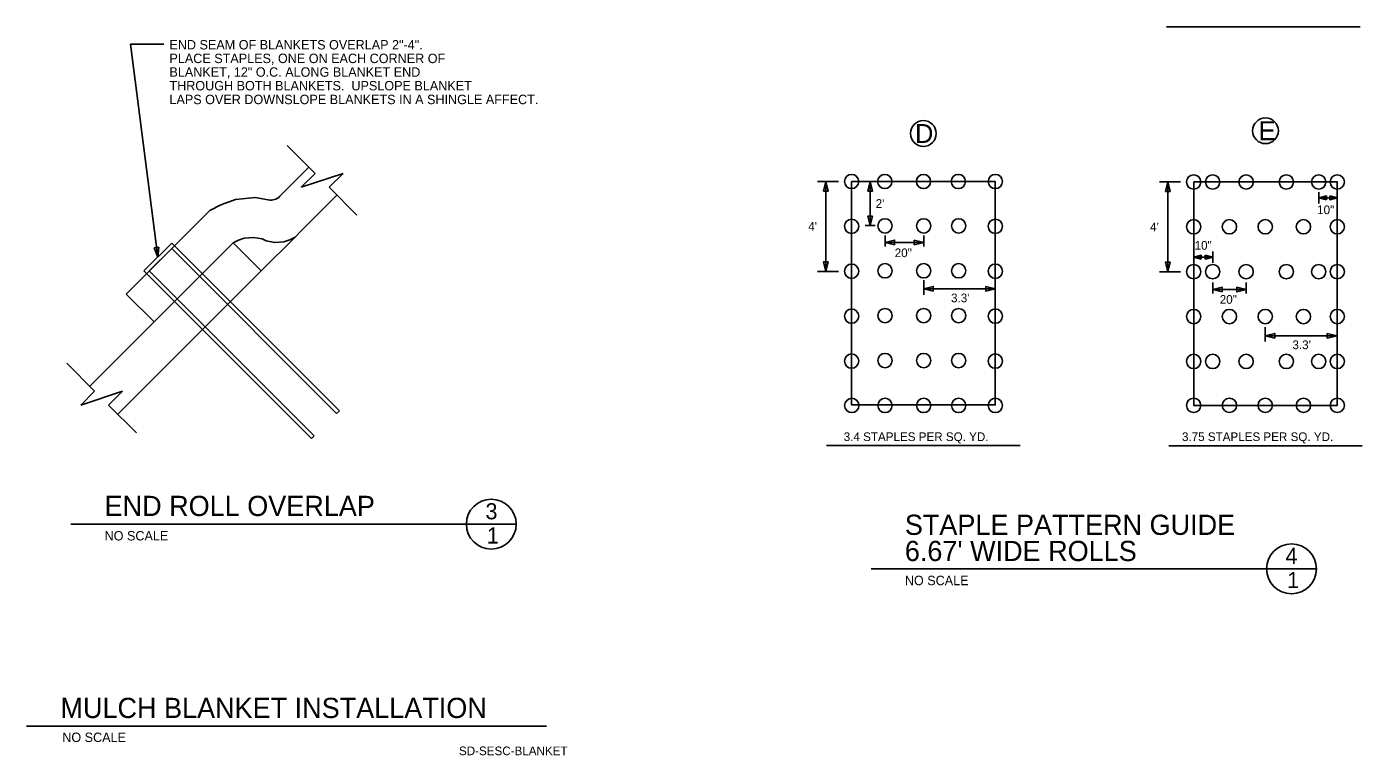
# Model space of a CAD drawing. Extents: x 27123946 to 27124151, y 1145898 to 1146027.
# Drawn here: x 27124033.3 to 27124150.6, y 1145898.2 to 1145962.3 of the extents above; entities that cross this region are included whole.
import ezdxf

# ---------------------------------------------------------------- set-up
doc = ezdxf.new("R2010")
doc.units = 0
for name, color, linetype in [('C-PVMT', 7, 'Continuous'), ('Default', 7, 'Continuous'), ('G-ANNO-CELL', 7, 'Continuous'), ('G-ANNO-TEXT', 7, 'Continuous'), ('G-ANNO-TTXT', 7, 'Continuous'), ('L-MISC-LINE', 7, 'Continuous'), ('L-SITE-SOIL', 7, 'Continuous')]:
    doc.layers.add(name, color=color, linetype=linetype)

msp = doc.modelspace()

# ---------------------------------------------------------------- linework, layer by layer
at = {"layer": 'C-PVMT'}
for p, q in [((27124060.52, 1145947.45), (27124057.37, 1145944.3)), ((27124042, 1145938.75), (27124049.35, 1145946.1)), ((27124038.8, 1145930.65), (27124051.4, 1145943.25)), ((27124051.4, 1145943.25), (27124053.86, 1145940.79)), ((27124053.86, 1145940.79), (27124041.26, 1145928.19)), ((27124044.46, 1145936.3), (27124042, 1145938.75))]:
    msp.add_line(p, q, dxfattribs=at)
for points in [[(27124055.51, 1145947.35), (27124058.06, 1145949.91)], [(27124050.72, 1145946.76), (27124051.62, 1145947.08), (27124053.34, 1145947.24), (27124054.48, 1145947.03)], [(27124049.35, 1145946.1), (27124050.33, 1145946.59)], [(27124051.4, 1145943.25), (27124051.88, 1145943.48), (27124052.38, 1145943.66), (27124053.18, 1145943.74), (27124053.94, 1145943.6), (27124054.12, 1145943.51)], [(27124057.37, 1145944.3), (27124056.84, 1145943.77), (27124056.37, 1145943.53), (27124055.86, 1145943.35), (27124055.06, 1145943.28), (27124054.31, 1145943.42), (27124054.12, 1145943.51)]]:
    msp.add_lwpolyline(points, dxfattribs=at)
for centre, radius, start, end in [((27124051.88, 1145943.48), 3.47, 109.5437, 116.4817), ((27124054.69, 1145948.17), 1.16, 259.4587, 315)]:
    msp.add_arc(centre, radius, start, end, dxfattribs=at)
at = {"layer": 'Default'}
for p, q in [((27124056.16, 1145951.81), (27124058.61, 1145949.36)), ((27124058.61, 1145949.36), (27124057.38, 1145948.14)), ((27124061.06, 1145949.36), (27124057.38, 1145948.14)), ((27124061.06, 1145949.36), (27124059.83, 1145948.14)), ((27124059.83, 1145948.14), (27124062.28, 1145945.69)), ((27124106.07, 1145948.65), (27124107.97, 1145948.65)), ((27124049.35, 1145946.1), (27124049.35, 1145946.1)), ((27124046, 1145943.24), (27124043.54, 1145940.79)), ((27124046, 1145943.24), (27124060.74, 1145928.5)), ((27124046, 1145942.75), (27124044.03, 1145940.79)), ((27124046, 1145942.75), (27124060.49, 1145928.26)), ((27124043.54, 1145940.79), (27124058.28, 1145926.05)), ((27124044.03, 1145940.79), (27124058.52, 1145926.29)), ((27124036.78, 1145932.67), (27124039.22, 1145930.22)), ((27124039.22, 1145930.22), (27124038, 1145929)), ((27124041.68, 1145930.22), (27124038, 1145929)), ((27124041.68, 1145930.22), (27124040.45, 1145929)), ((27124040.45, 1145929), (27124042.9, 1145926.55)), ((27124060.74, 1145928.5), (27124060.49, 1145928.26)), ((27124058.52, 1145926.29), (27124058.28, 1145926.05))]:
    msp.add_line(p, q, dxfattribs=at)
at = {"layer": 'G-ANNO-CELL'}
for centre in [(27124074.09, 1145918.52), (27124144.43, 1145914.59)]:
    msp.add_circle(centre, 2.19, dxfattribs=at)
at = {"layer": 'G-ANNO-TEXT'}
for p, q in [((27124133.44, 1145962.26), (27124150.45, 1145962.26)), ((27124044.77, 1145942.01), (27124042.39, 1145960.73)), ((27124042.39, 1145960.73), (27124045.3, 1145960.73)), ((27124104.6, 1145948.65), (27124102.76, 1145948.65)), ((27124103.5, 1145940.75), (27124103.5, 1145948.65)), ((27124107.39, 1145944.78), (27124107.39, 1145948.65)), ((27124134.66, 1145948.61), (27124132.81, 1145948.61)), ((27124133.55, 1145940.72), (27124133.55, 1145948.61)), ((27124146.82, 1145946.73), (27124146.82, 1145947.72)), ((27124148.45, 1145947.22), (27124146.82, 1145947.22)), ((27124106.94, 1145944.78), (27124107.84, 1145944.78)), ((27124108.7, 1145943.9), (27124108.7, 1145942.93)), ((27124108.7, 1145943.3), (27124112.1, 1145943.3)), ((27124112.1, 1145943.9), (27124112.1, 1145942.93)), ((27124137.5, 1145941.5), (27124137.5, 1145942.49)), ((27124137.5, 1145942), (27124135.83, 1145942)), ((27124104.6, 1145940.75), (27124102.76, 1145940.75)), ((27124112.1, 1145939.98), (27124112.1, 1145938.7)), ((27124134.66, 1145940.72), (27124132.81, 1145940.72)), ((27124137.5, 1145939.76), (27124137.5, 1145938.79)), ((27124140.44, 1145939.76), (27124140.44, 1145938.79)), ((27124112.1, 1145939.22), (27124118.39, 1145939.22)), ((27124137.5, 1145939.15), (27124140.44, 1145939.15)), ((27124142.12, 1145935.85), (27124142.12, 1145934.58)), ((27124142.12, 1145935.09), (27124148.4, 1145935.09)), ((27124103.56, 1145925.43), (27124120.58, 1145925.43)), ((27124133.63, 1145925.4), (27124150.65, 1145925.4)), ((27124037.14, 1145918.52), (27124076.28, 1145918.52)), ((27124107.48, 1145914.59), (27124146.62, 1145914.59)), ((27124033.25, 1145900.76), (27124078.95, 1145900.76))]:
    msp.add_line(p, q, dxfattribs=at)
for points in [[(27124103.29, 1145947.81), (27124103.5, 1145948.65), (27124103.71, 1145947.81)], [(27124107.19, 1145947.81), (27124107.39, 1145948.65), (27124107.6, 1145947.81)], [(27124133.34, 1145947.78), (27124133.55, 1145948.61), (27124133.76, 1145947.78)], [(27124147.49, 1145947.05), (27124146.82, 1145947.22), (27124147.49, 1145947.39)], [(27124147.79, 1145947.39), (27124148.45, 1145947.22), (27124147.79, 1145947.05)], [(27124107.6, 1145945.61), (27124107.39, 1145944.78), (27124107.19, 1145945.61)], [(27124109.54, 1145943.09), (27124108.7, 1145943.3), (27124109.54, 1145943.5)], [(27124111.27, 1145943.5), (27124112.1, 1145943.3), (27124111.27, 1145943.09)], [(27124044.87, 1145942.87), (27124044.77, 1145942.01), (27124044.46, 1145942.81)], [(27124136.49, 1145941.83), (27124135.83, 1145942), (27124136.49, 1145942.16)], [(27124136.84, 1145942.16), (27124137.5, 1145942), (27124136.84, 1145941.83)], [(27124103.71, 1145941.58), (27124103.5, 1145940.75), (27124103.29, 1145941.58)], [(27124133.76, 1145941.55), (27124133.55, 1145940.72), (27124133.34, 1145941.55)], [(27124112.94, 1145939.01), (27124112.1, 1145939.22), (27124112.94, 1145939.43)], [(27124117.55, 1145939.43), (27124118.39, 1145939.22), (27124117.55, 1145939.01)], [(27124138.34, 1145938.94), (27124137.5, 1145939.15), (27124138.34, 1145939.36)], [(27124139.61, 1145939.36), (27124140.44, 1145939.15), (27124139.61, 1145938.94)], [(27124142.96, 1145934.88), (27124142.12, 1145935.09), (27124142.96, 1145935.3)], [(27124147.57, 1145935.3), (27124148.4, 1145935.09), (27124147.57, 1145934.88)]]:
    msp.add_lwpolyline(points, close=True, dxfattribs=at)
for centre in [(27124112.07, 1145952.87), (27124142.14, 1145953.11)]:
    msp.add_circle(centre, 1.13, dxfattribs=at)
at = {"layer": 'L-MISC-LINE'}
msp.add_lwpolyline([(27124105.76, 1145948.65), (27124118.39, 1145948.65), (27124118.39, 1145929.01), (27124105.76, 1145929.01)], close=True, dxfattribs=at)
for centre in [(27124105.76, 1145948.65), (27124108.68, 1145948.65), (27124112.08, 1145948.65), (27124115.14, 1145948.65), (27124118.39, 1145948.65), (27124135.83, 1145948.61), (27124137.5, 1145948.61), (27124140.44, 1145948.61), (27124143.97, 1145948.61), (27124146.82, 1145948.61), (27124148.45, 1145948.61), (27124105.76, 1145944.71), (27124108.7, 1145944.75), (27124112.1, 1145944.75), (27124115.17, 1145944.75), (27124118.39, 1145944.71), (27124135.83, 1145944.67), (27124138.97, 1145944.67), (27124142.12, 1145944.67), (27124145.48, 1145944.67), (27124148.45, 1145944.67), (27124105.76, 1145940.76), (27124108.7, 1145940.8), (27124112.1, 1145940.8), (27124115.17, 1145940.8), (27124118.39, 1145940.76), (27124135.83, 1145940.72), (27124137.5, 1145940.72), (27124140.44, 1145940.72), (27124143.97, 1145940.72), (27124146.82, 1145940.72), (27124148.45, 1145940.72), (27124105.76, 1145936.81), (27124108.7, 1145936.86), (27124112.1, 1145936.86), (27124115.17, 1145936.86), (27124118.39, 1145936.81), (27124135.83, 1145936.78), (27124138.97, 1145936.78), (27124142.12, 1145936.78), (27124145.48, 1145936.78), (27124148.45, 1145936.78), (27124105.76, 1145932.86), (27124108.7, 1145932.91), (27124112.1, 1145932.91), (27124115.17, 1145932.91), (27124118.39, 1145932.86), (27124135.83, 1145932.83), (27124137.5, 1145932.83), (27124140.44, 1145932.83), (27124143.97, 1145932.83), (27124146.82, 1145932.83), (27124148.45, 1145932.83), (27124105.78, 1145928.96), (27124108.7, 1145928.96), (27124112.1, 1145928.96), (27124115.17, 1145928.96), (27124118.39, 1145928.96), (27124135.83, 1145928.97), (27124138.97, 1145928.97), (27124142.12, 1145928.97), (27124145.48, 1145928.97), (27124148.45, 1145928.97)]:
    msp.add_circle(centre, 0.629, dxfattribs=at)
at = {"layer": 'L-SITE-SOIL'}
msp.add_line((27124053.86, 1145940.79), (27124056.84, 1145943.77), dxfattribs=at)
msp.add_lwpolyline([(27124135.83, 1145948.61), (27124148.45, 1145948.61), (27124148.45, 1145928.97), (27124135.83, 1145928.97)], close=True, dxfattribs=at)

# ---------------------------------------------------------------- texts
at = {"layer": 'G-ANNO-CELL'}
for s, p in [('3 ', (27124073.58, 1145918.95)), ('1 ', (27124073.7, 1145916.82)), ('4 ', (27124143.9, 1145915.03)), ('1 ', (27124144.04, 1145912.9))]:
    msp.add_text(s, height=1.417, dxfattribs=at).set_placement(p)
at = {"layer": 'G-ANNO-TEXT'}
for s, height, p in [('END SEAM OF BLANKETS OVERLAP 2"-4".  ', 0.828, (27124045.8, 1145960.26)), ('PLACE STAPLES, ONE ON EACH CORNER OF', 0.828, (27124045.8, 1145959.06)), ('BLANKET, 12" O.C. ALONG BLANKET END', 0.828, (27124045.8, 1145957.86)), ('THROUGH BOTH BLANKETS.  UPSLOPE BLANKET', 0.828, (27124045.8, 1145956.66)), ('LAPS OVER DOWNSLOPE BLANKETS IN A SHINGLE AFFECT.', 0.828, (27124045.8, 1145955.45)), ('E', 1.66, (27124141.54, 1145952.28)), ('D', 1.66, (27124111.34, 1145952.04)), ("2'", 0.765, (27124107.88, 1145946.33)), ('10"', 0.765, (27124146.68, 1145945.78)), ("4'", 0.765, (27124101.95, 1145944.32)), ("4'", 0.765, (27124132, 1145944.28)), ('10"', 0.765, (27124135.91, 1145942.65)), ('20"', 0.765, (27124109.55, 1145942)), ("3.3'", 0.765, (27124114.5, 1145938.03)), ('20"', 0.765, (27124138.12, 1145937.9)), ("3.3'", 0.765, (27124144.51, 1145933.91)), ('3.4 STAPLES PER SQ. YD.', 0.7645, (27124105.07, 1145925.83)), ('3.75 STAPLES PER SQ. YD.', 0.7645, (27124134.8, 1145925.83)), ('NO SCALE', 0.828, (27124040.1, 1145917.09)), ('NO SCALE', 0.828, (27124110.44, 1145913.16)), ('NO SCALE', 0.828, (27124036.38, 1145899.37)), ('SD-SESC-BLANKET', 0.7645, (27124071.25, 1145898.21))]:
    msp.add_text(s, height=height, dxfattribs=at).set_placement(p)
at = {"layer": 'G-ANNO-TTXT'}
for s, p in [('END ROLL OVERLAP', (27124040.1, 1145919.24)), ('STAPLE PATTERN GUIDE', (27124110.44, 1145917.58)), ("6.67' WIDE ROLLS", (27124110.44, 1145915.28)), ('MULCH BLANKET INSTALLATION', (27124036.22, 1145901.48))]:
    msp.add_text(s, height=1.776, dxfattribs=at).set_placement(p)

doc.saveas('drawing.dxf')
